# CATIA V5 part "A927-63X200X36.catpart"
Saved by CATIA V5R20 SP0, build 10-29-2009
Part number: A927-63X200X36
Source: Unknown
Property "A": "36.000"
Property "ARTICLENO": "A927-63X200X36"
Property "BOMINFO": "A927-63X200X36"
Property "CODE": "A927-63X200X36"
Property "CREATOR": "CADENAS GmbH"
Property "D": "14.000"
Property "D1": "20.000"
Property "F": "18.000"
Property "FORM": "A"
Property "L": "200.000"
Property "L1": "90.000"
Property "L2": "20.000"
Property "L3": "50.000"
Property "LINA": "A927-63X200X36"
Property "NB": "A927-63X200X36"
Property "NBSYN": "$CODE."
Property "NN": "A927"
Property "NT": "VDI 3387 Removable Die Heels, steel and self-lubricating"
Property "R": "16.000"
Property "S": "36.000"
Property "SUPPLIER": "CF"
Property "T": "16.000"
Property "W": "63.000"
Bounding box of the stored display mesh (mm): x -31.5 to 31.5, y 0 to 200, z -36 to 0
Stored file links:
  C:\Users\borellobunino\Desktop\3D X SITO CF\A927\GSB_OILLESS_G2290506320036\CATIAV5\A927-63X200X36.catpart
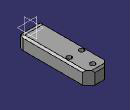
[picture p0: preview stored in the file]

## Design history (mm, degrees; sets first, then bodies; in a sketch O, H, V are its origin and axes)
Body1 "Geometry.1" (main body)
  Solid1 "A927-63X200X36.catpart": solid without history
